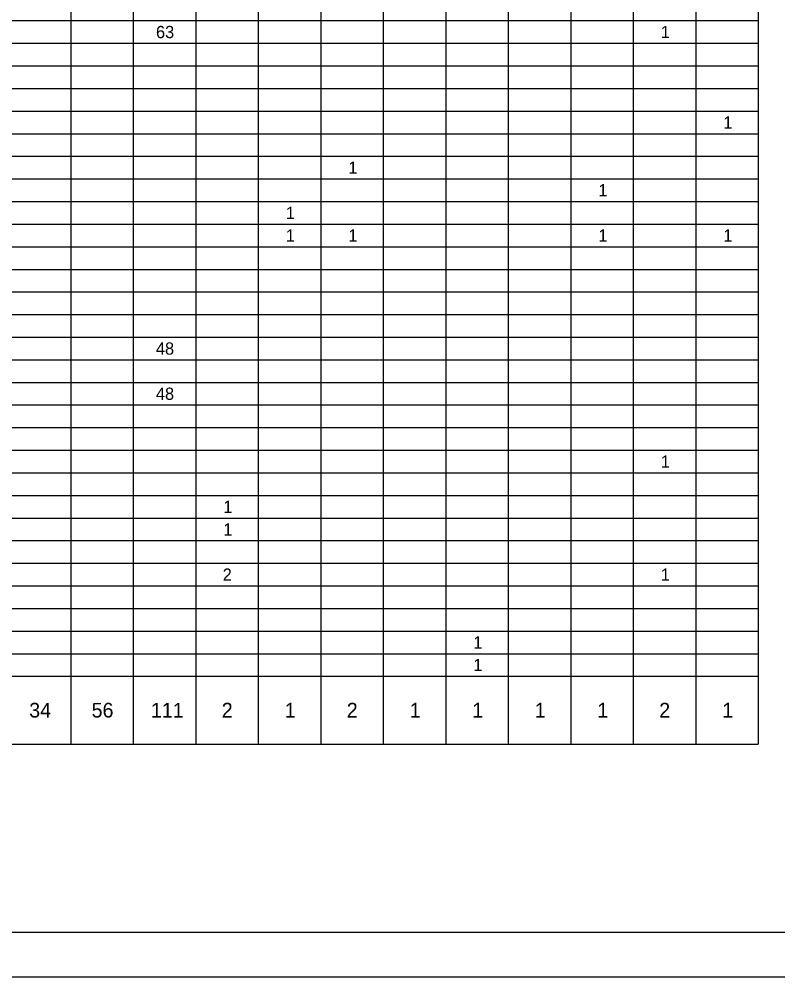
# Model space of a CAD drawing. Extents: x 0 to 34, y 0 to 22.
# Drawn here: x 16.88 to 25.44, y 0 to 10.8 of the extents above; entities that cross this region are included whole.
import ezdxf

# ---------------------------------------------------------------- set-up
doc = ezdxf.new("R2010")
doc.units = 0
for name, color, linetype in [('SH_Border', 7, 'Continuous'), ('SH_Cut_Line', 7, 'Continuous'), ('SH_Text', 7, 'Continuous')]:
    doc.layers.add(name, color=color, linetype=linetype)

msp = doc.modelspace()

# ---------------------------------------------------------------- linework, layer by layer
at = {"layer": 'SH_Border'}
msp.add_lwpolyline([(1.5, 21.5), (33.5, 21.5), (33.5, 0.5), (1.5, 0.5)], close=True, dxfattribs=at)
at = {"layer": 'SH_Cut_Line'}
msp.add_lwpolyline([(0, 0), (34, 0), (34, 22), (0, 22)], close=True, dxfattribs=at)
at = {"layer": 'SH_Text'}
for p, q in [((25.22, 21), (25.22, 2.625)), ((17.465, 20.745), (17.465, 2.625)), ((18.17, 20.745), (18.17, 2.625)), ((18.875, 20.745), (18.875, 2.625)), ((19.58, 20.745), (19.58, 2.625)), ((20.285, 20.745), (20.285, 2.625)), ((20.99, 20.745), (20.99, 2.625)), ((21.695, 20.745), (21.695, 2.625)), ((22.4, 20.745), (22.4, 2.625)), ((23.105, 20.745), (23.105, 2.625)), ((23.81, 20.745), (23.81, 2.625)), ((24.515, 20.745), (24.515, 2.625)), ((7.595, 10.785), (25.22, 10.785)), ((7.595, 10.53), (25.22, 10.53)), ((7.595, 10.275), (25.22, 10.275)), ((7.595, 10.02), (25.22, 10.02)), ((7.595, 9.765), (25.22, 9.765)), ((7.595, 9.51), (25.22, 9.51)), ((7.595, 9.255), (25.22, 9.255)), ((7.595, 9), (25.22, 9)), ((7.595, 8.745), (25.22, 8.745)), ((7.595, 8.49), (25.22, 8.49)), ((7.595, 8.235), (25.22, 8.235)), ((7.595, 7.98), (25.22, 7.98)), ((7.595, 7.725), (25.22, 7.725)), ((7.595, 7.47), (25.22, 7.47)), ((7.595, 7.215), (25.22, 7.215)), ((7.595, 6.96), (25.22, 6.96)), ((7.595, 6.705), (25.22, 6.705)), ((7.595, 6.45), (25.22, 6.45)), ((7.595, 6.195), (25.22, 6.195)), ((7.595, 5.94), (25.22, 5.94)), ((7.595, 5.685), (25.22, 5.685)), ((7.595, 5.43), (25.22, 5.43)), ((7.595, 5.175), (25.22, 5.175)), ((7.595, 4.92), (25.22, 4.92)), ((7.595, 4.665), (25.22, 4.665)), ((7.595, 4.41), (25.22, 4.41)), ((7.595, 4.155), (25.22, 4.155)), ((7.595, 3.9), (25.22, 3.9)), ((7.595, 3.645), (25.22, 3.645)), ((7.595, 3.39), (25.22, 3.39)), ((7.595, 2.625), (25.22, 2.625))]:
    msp.add_line(p, q, dxfattribs=at)

# ---------------------------------------------------------------- texts
for s, height, p in [('63', 0.138, (18.426, 10.588)), ('1', 0.138, (24.121, 10.588)), ('1', 0.138, (24.826, 9.568)), ('1', 0.138, (20.596, 9.058)), ('1', 0.138, (23.416, 8.803)), ('1', 0.138, (19.891, 8.548)), ('1', 0.138, (19.891, 8.293)), ('1', 0.138, (20.596, 8.293)), ('1', 0.138, (23.416, 8.293)), ('1', 0.138, (24.826, 8.293)), ('48', 0.138, (18.425, 7.018)), ('48', 0.138, (18.425, 6.508)), ('1', 0.138, (24.121, 5.743)), ('1', 0.138, (19.186, 5.233)), ('1', 0.138, (19.186, 4.978)), ('2', 0.138, (19.179, 4.468)), ('1', 0.138, (24.121, 4.468)), ('1', 0.138, (22.006, 3.703)), ('1', 0.138, (22.006, 3.448)), ('34', 0.1656, (16.996, 2.925)), ('56', 0.1656, (17.7, 2.925)), ('111', 0.1656, (18.369, 2.925)), ('2', 0.166, (19.168, 2.925)), ('1', 0.166, (19.879, 2.925)), ('2', 0.166, (20.578, 2.925)), ('1', 0.166, (21.289, 2.925)), ('1', 0.166, (21.994, 2.925)), ('1', 0.166, (22.699, 2.925)), ('1', 0.166, (23.404, 2.925)), ('2', 0.166, (24.103, 2.925)), ('1', 0.166, (24.814, 2.925))]:
    msp.add_text(s, height=height, dxfattribs=at).set_placement(p)

doc.saveas('drawing.dxf')
